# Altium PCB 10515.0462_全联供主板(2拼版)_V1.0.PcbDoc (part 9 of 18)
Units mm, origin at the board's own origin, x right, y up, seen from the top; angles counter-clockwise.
Board outline 282 x 198 mm, 2 copper layers (Top Layer, Bottom Layer); 716 components, 0 nets, 2364 pads, 1800 vias.
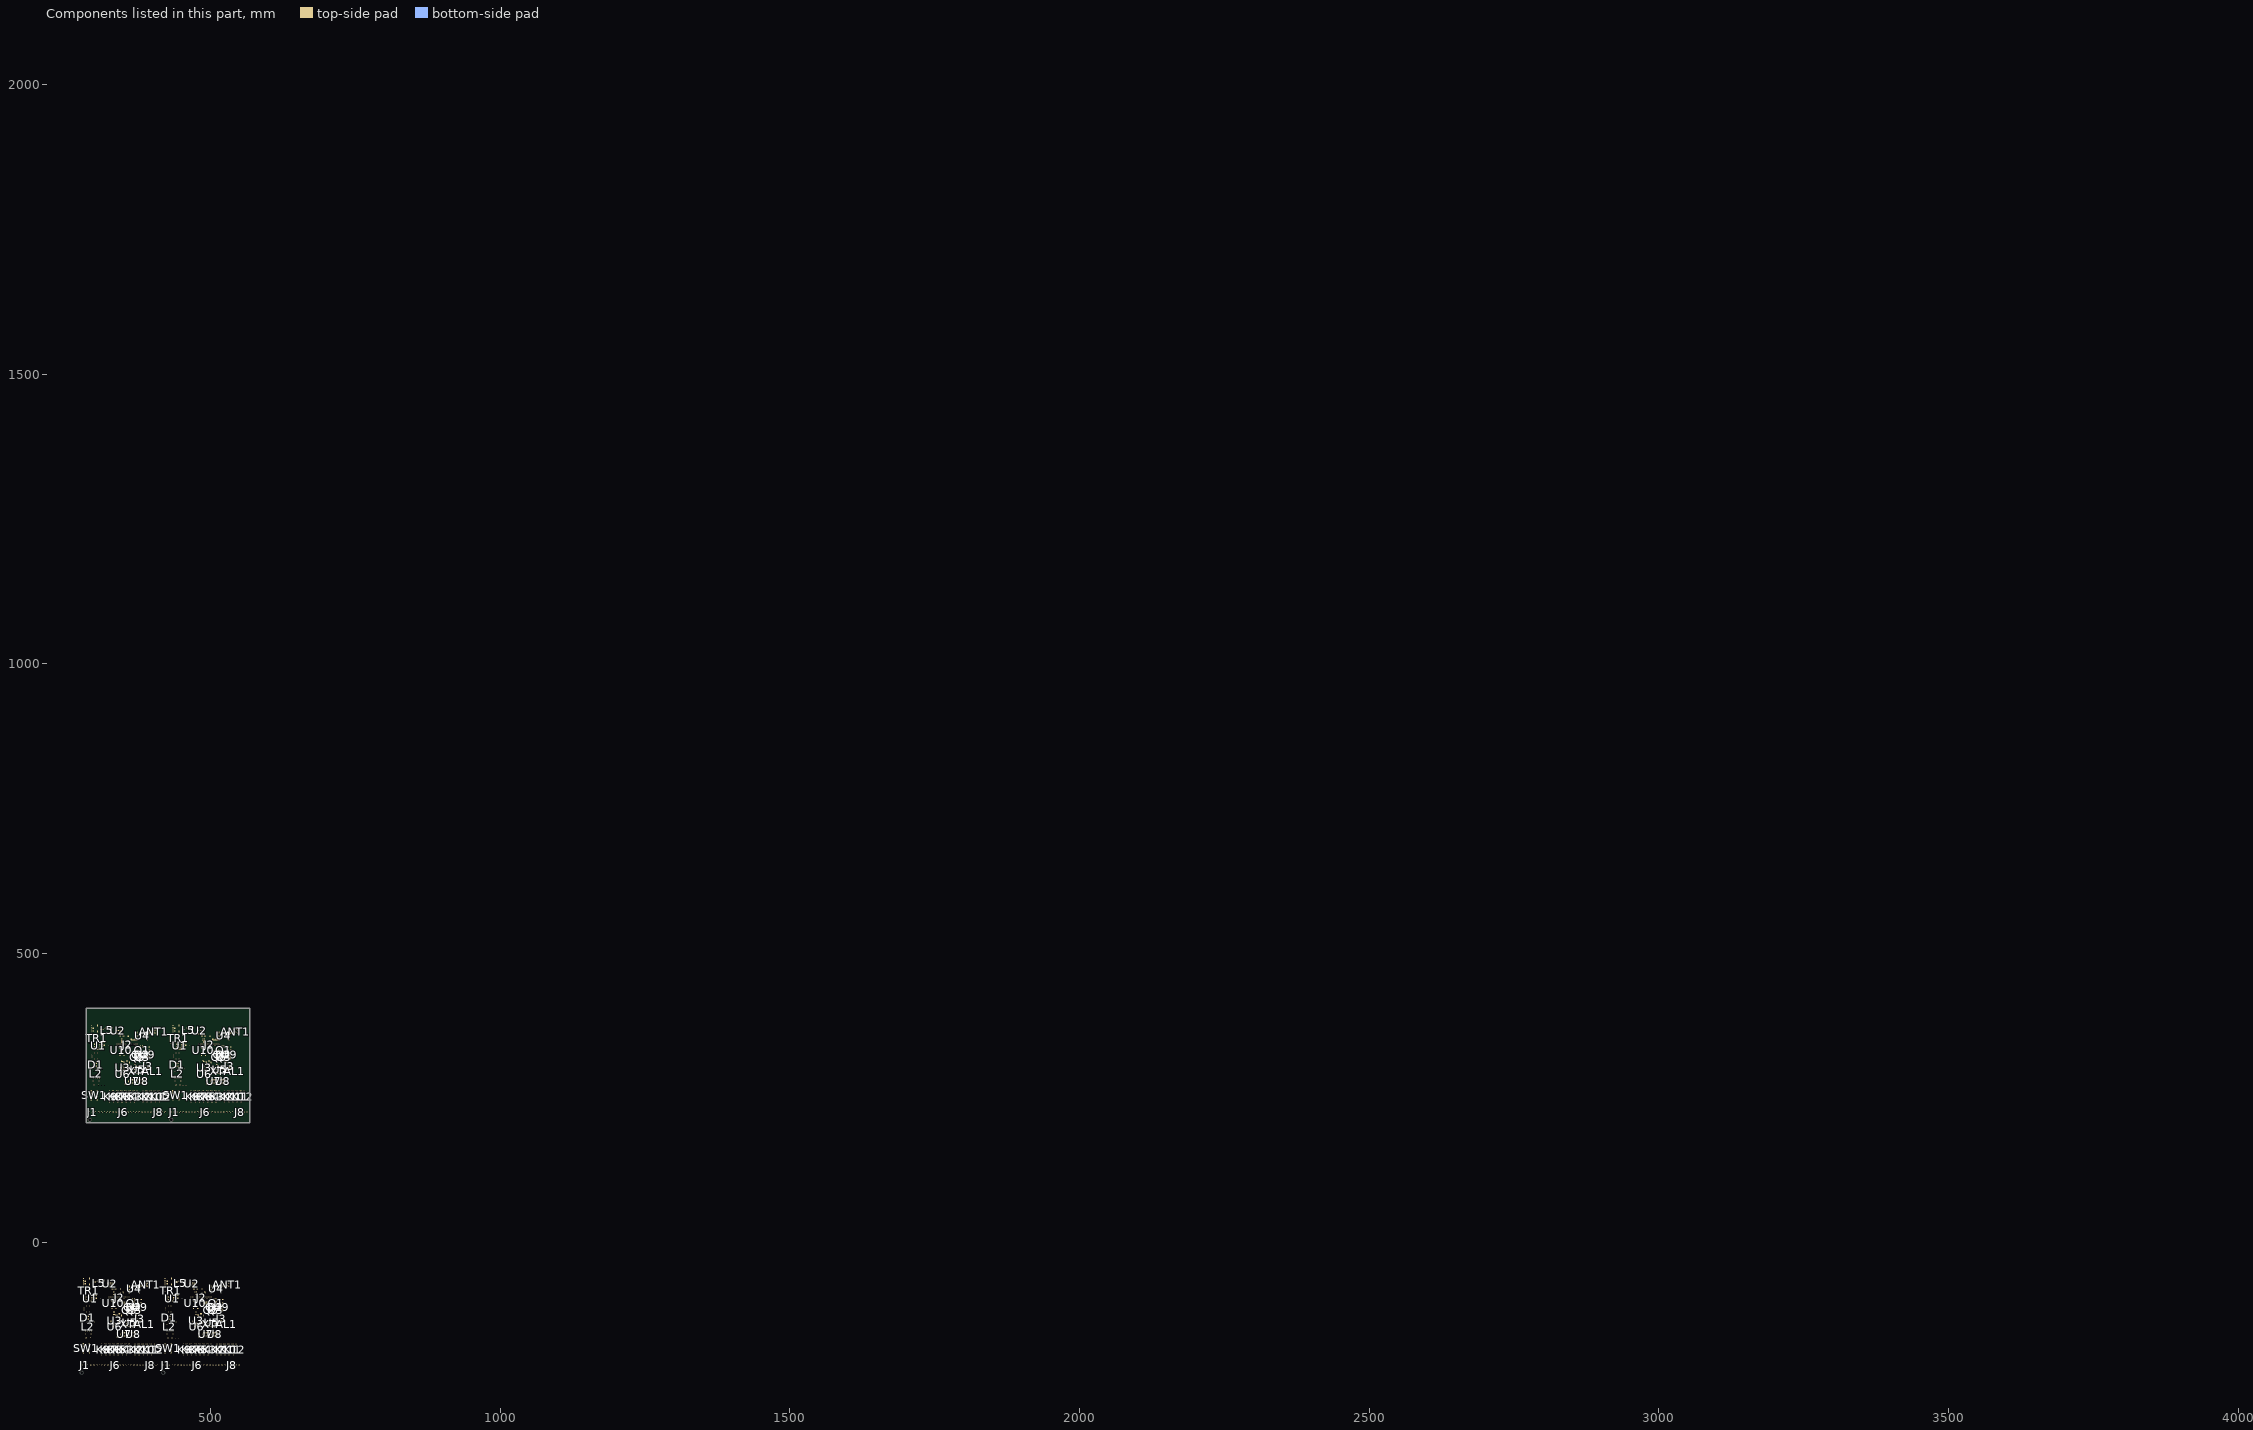
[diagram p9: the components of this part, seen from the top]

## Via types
v1: diameter 0.7, hole 0.4, Top Layer to Bottom Layer, tented both sides, 1800 vias

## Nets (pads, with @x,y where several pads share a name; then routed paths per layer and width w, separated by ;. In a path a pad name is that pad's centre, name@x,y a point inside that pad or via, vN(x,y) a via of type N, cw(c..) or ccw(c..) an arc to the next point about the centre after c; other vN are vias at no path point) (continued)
copper on no net: (continued)
  Top Layer w0.65: 285.476,-64.542 287.715,-64.542 290.89,-61.367 290.89,-62.336 295.122,-66.568 295.509,-66.568 ; 290.89,-71.667 290.89,-71.51 292.366,-70.035 ; 291.064,-69.749 292.614,-68.2 297.083,-68.2 296.55,-68.733 292.842,-68.733 292.461,-69.114 ; 291.318,-61.875 295.509,-66.066 296.601,-66.066 ; 291.318,-61.113 296.754,-66.549 296.837,-66.549 296.96,-66.426 ; 291.572,-70.003 292.144,-69.431 ; 292.017,-63.462 292.017,-64.288 ; 292.652,-64.923 292.017,-64.923 ; 293.35,-64.034 295.001,-65.685 296.22,-65.685 297.083,-66.549 ; 293.604,-66.568 293.604,-66.51 292.017,-64.923 ; 294.297,-66.568 292.017,-64.288 ; 295.691,-68.733 ccw(c295.691,-66.845) 297.026,-68.18 ; 295.813,-66.066 cw(c295.813,-67.78) 297.026,-66.568 295.509,-66.568 ; 297.083,-66.429 ccw(c297.083,-65.893) 297.462,-66.272 ; 297.141,-66.568 cw(c298.353,-67.78) 298.353,-66.066 ; 297.16,-68.479 296.208,-69.431 ; 297.164,-66.519 cw(c297.668,-66.573) 297.668,-66.066 ; 298.801,-66.565 ccw(c297.668,-67.601) 297.668,-66.066 ; 298.861,-66.549 298.379,-66.066 297.668,-66.066 ; 299.105,372.053 301.344,372.053 304.519,375.228 304.519,374.259 308.751,370.027 309.138,370.027 ; 299.738,-66.637 cw(c300.203,-67.102) 300.547,-66.542 ; 300.097,-65.669 cw(c301.224,-66.795) v1@301.224,-65.202 ; 300.272,-65.494 cw(c301.023,-66.246) v1@301.219,-65.202 ; 300.532,-66.415 ccw(c299.473,-65.356) v1@300.97,-65.356 ; v1@300.571,-65.195 cw(c299.609,-66.157) 300.97,-66.157 ; 300.589,-66.654 cw(c302.547,-66.654) v1@301.241,-65.196 ; 300.589,-66.391 ccw(c300.589,-65.336) 301.335,-66.082 ; v1@300.594,-65.202 cw(c300.79,-66.246) 301.542,-65.494 ; 300.612,-66.394 cw(c300.82,-65.685) 300.081,-65.685 ; 300.97,-65.851 cw(c301.898,-65.851) v1@301.242,-65.195 ; 300.995,-66.549 ccw(c300.995,-62.838) 303.619,-65.462 cw(c302.467,-64.309) 302.467,-65.939 cw(c302.467,-67.569) 303.619,-66.416 ; v1@301.206,-65.195 cw(c300.551,-65.851) 301.478,-65.851 ; 302.564,-66.549 ccw(c302.564,-64.407) 304.078,-65.921 ; 304.519,364.928 304.519,365.085 305.995,366.561 ; 304.693,366.846 306.242,368.396 310.712,368.396 310.178,367.862 306.471,367.862 306.09,367.481 ; 304.947,374.72 309.138,370.529 310.229,370.529 ; 304.947,375.482 310.382,370.047 310.466,370.047 310.589,370.17 ; 305.201,366.592 305.772,367.164 ; 305.645,373.133 305.645,372.307 ; 306.28,371.672 305.645,371.672 ; 306.979,372.561 308.63,370.91 309.848,370.91 310.712,370.047 ; 307.233,370.027 307.233,370.085 305.645,371.672 ; 307.925,370.027 305.645,372.307 ; 308.494,-66.416 cw(c307.342,-67.569) 308.971,-67.569 cw(c310.601,-67.569) 309.448,-66.416 ; 308.504,-73.001 ccw(c307.457,-71.908) 308.971,-71.908 ccw(c310.485,-71.908) 309.438,-73.001 ; 308.735,-66.571 cw(c308.266,-67.827) 309.606,-67.827 ; 308.962,-65.962 cw(c308.616,-66.89) 309.606,-66.89 ; 308.971,-66.614 cw(c308.971,-69.163) 310.774,-67.361 ; 308.996,-73.486 cw(c310.514,-73.292) 309.432,-72.209 ; 308.998,-72.815 ccw(c309.059,-71.234) 310.178,-72.353 ; 309.281,-72.889 cw(c309.941,-71.613) 308.504,-71.613 ; 309.32,367.862 ccw(c309.32,369.75) 310.654,368.415 ; 309.442,370.529 cw(c309.442,368.815) 310.654,370.027 309.138,370.027 ; 309.606,-67.082 310.368,-67.844 312.4,-67.844 ; 309.635,-66.059 ccw(c311.337,-66.367) 310.114,-67.59 ; 309.641,-73.403 cw(c312.174,-73.079) 310.368,-71.273 ; 309.646,-73.489 cw(c311.107,-73.489) 310.074,-72.456 ; 309.646,-65.939 ccw(c310.356,-65.939) 309.854,-66.441 ; 310.712,370.166 ccw(c310.712,370.702) 311.091,370.323 ; 310.769,370.027 cw(c311.982,368.815) 311.982,370.529 ; 310.789,368.116 309.836,367.164 ; 310.793,370.076 cw(c311.297,370.023) 311.297,370.529 ; 312.43,370.03 ccw(c311.297,368.995) 311.297,370.529 ; 312.49,370.047 312.007,370.529 311.297,370.529 ; 313.035,-68.479 314.813,-66.701 314.813,-66.574 ; 313.035,-67.844 313.035,-67.543 315.655,-64.923 ; 313.162,-67.844 314.813,-66.193 ; 313.257,-67.241 cw(c315.655,-69.64) 315.655,-66.248 ; 313.282,-66.581 cw(c315.655,-68.954) 315.655,-65.598 ; 313.289,-71.781 314.305,-72.797 314.305,-74.448 315.08,-75.223 315.655,-75.223 ; 313.367,369.958 cw(c313.832,369.493) 314.175,370.054 ; 313.393,-67.185 cw(c315.655,-69.447) 315.655,-66.248 ; 313.67,-67.844 312.4,-67.844 ; 313.71,370.91 ccw(c314.449,370.91) 314.241,370.201 ; 313.726,370.927 cw(c314.853,369.8) v1@314.853,371.393 ; 313.9,371.101 cw(c314.652,370.35) v1@314.848,371.394 ; 314.124,-66.882 cw(c315.655,-68.414) 315.655,-66.248 ; 314.16,370.181 ccw(c313.102,371.239) v1@314.599,371.239 ; v1@314.2,371.401 cw(c313.238,370.438) 314.599,370.438 ; 314.218,369.942 cw(c316.175,369.942) v1@314.87,371.4 ; 314.218,370.204 ccw(c314.218,371.259) 314.964,370.513 ; v1@314.223,371.394 cw(c314.419,370.35) 315.17,371.101 ; 314.366,-66.132 cw(c315.655,-67.421) 315.655,-65.598 ; 314.392,-65.471 cw(c315.655,-66.735) 315.655,-64.948 ; 314.432,-72.543 313.67,-71.781 310.749,-71.781 310.178,-72.352 ; 314.503,-66.075 cw(c315.655,-67.228) 315.655,-65.598 ; 314.599,370.745 cw(c315.526,370.745) v1@314.871,371.401 ; 314.624,370.047 ccw(c314.624,373.758) 317.248,371.134 cw(c316.095,372.286) 316.095,370.656 cw(c316.095,369.027) 317.248,370.179 ; 314.663,-66.851 ccw(c313.534,-65.723) 315.13,-65.723 ; 314.813,-74.261 ccw(c315.817,-74.261) 315.107,-74.971 ; 314.813,-72.692 ccw(c317.386,-72.692) 315.567,-74.511 ; 314.813,-72.289 313.797,-71.273 310.368,-71.273 308.971,-72.67 308.971,-73.489 ; 314.813,-71.527 314.051,-70.765 310.114,-70.765 308.971,-71.908 308.971,-73.489 ; 314.813,-71.123 ccw(c318.955,-71.123) 316.026,-74.052 cw(c316.923,-73.156) 315.655,-73.156 cw(c314.388,-73.156) 315.284,-74.052 ; 314.813,-68.123 cw(c317.079,-68.123) 315.923,-66.175 ; 314.813,-67.971 313.924,-68.86 ; 314.813,-67.336 313.67,-68.479 310.368,-68.479 309.606,-67.717 309.606,-66.574 308.971,-65.939 ; 314.813,-66.982 cw(c316.402,-66.982) 315.591,-65.615 ; v1@314.835,371.401 cw(c314.179,370.745) 315.107,370.745 ; 314.881,-66.633 ccw(c314.226,-65.978) 315.138,-65.815 ; 314.94,-64.923 312.527,-67.336 310.749,-67.336 309.352,-65.939 308.971,-65.939 ; 315.284,-75.594 ccw(c314.388,-76.49) 314.388,-75.223 ccw(c314.388,-73.956) 315.284,-74.852 ; 315.321,-75.223 314.318,-75.223 313.924,-74.829 313.924,-73.305 312.972,-72.352 310.178,-72.352 ; 315.325,-74.015 ccw(c313.829,-72.162) 316.21,-72.162 ; 315.465,-73.934 ccw(c314.827,-72.289) 316.591,-72.289 ; 315.578,-74.522 ccw(c316.044,-73.925) 316.579,-74.46 ; 315.655,-65.859 315.655,-64.923 ; 315.7,-74.54 ccw(c315.196,-73.238) 316.591,-73.238 ; 315.734,-74.52 ccw(c314.928,-73.523) 316.21,-73.523 ; 315.935,-75.146 ccw(c315.564,-74.188) 316.591,-74.188 ; 315.978,-74.009 ccw(c316.5,-73.34) 317.099,-73.94 ; 316.026,-66.094 ccw(c316.923,-66.99) 315.655,-66.99 ccw(c314.388,-66.99) 315.284,-66.094 cw(c313.354,-68.024) 316.083,-68.024 ; 316.106,-75.491 cw(c316.578,-75.772) 316.578,-75.223 ; 316.106,-74.955 ccw(c316.578,-74.674) 316.578,-75.223 ; 316.18,-65.723 ccw(c318.162,-65.723) 316.761,-67.125 ; 316.193,370.047 ccw(c316.193,372.189) 317.707,370.674 ; 317.353,-71.527 316.591,-72.289 316.591,-74.575 315.943,-75.223 315.655,-75.223 ; 317.516,-68.733 cw(c317.516,-70.094) v1@318.478,-69.132 ; 317.933,-69.278 ccw(c317.933,-67.609) v1@319.113,-68.789 ; 317.988,-71.527 317.099,-72.416 317.099,-73.94 ; 318.04,-69.278 ccw(c318.04,-68.658) v1@318.478,-69.096 ; 318.274,-68.638 cw(c317.798,-69.114) v1@318.471,-69.114 ; v1@318.514,-69.132 cw(c319.476,-70.094) 319.476,-68.733 ; v1@318.514,-69.096 ccw(c318.952,-68.658) 318.952,-69.278 ; v1@318.517,-69.128 cw(c319.131,-69.554) v1(319.131,-68.807) 318.443,-68.807 316.083,-66.447 ; 318.517,-68.733 cw(c318.517,-70.653) v1@319.875,-69.295 ; v1@319.154,-68.797 ccw(c319.893,-68.47) v1(319.893,-69.278) ; 319.675,-68.733 cw(c319.675,-70.094) v1@320.637,-69.132 ; v1@319.915,-69.29 cw(c320.872,-69.834) 320.872,-68.733 ; v1@320.199,-69.278 ccw(c320.199,-68.658) v1@320.637,-69.096 ; 320.285,-71.527 ccw(c320.285,-69.418) 321.776,-70.909 ; v1@320.673,-69.096 ccw(c321.111,-68.658) 321.111,-69.278 ; 320.909,-72.416 320.655,-72.162 ; 320.909,-71.867 321.834,-70.942 ; 321.1,-68.961 ccw(c321.635,-68.425) 321.815,-69.161 ; 321.157,-70.809 ccw(c321.48,-70.486) 321.78,-70.829 ; 321.29,-70.942 320.859,-70.511 316.464,-70.511 315.655,-71.32 315.655,-72.543 ; 321.417,-69.278 320.872,-68.733 ; 321.753,-72.67 321.753,-72.031 321.249,-71.527 ; 321.834,-70.929 321.834,-70.942 ; 321.834,-69.278 v1(319.893,-69.278) ; 321.847,-70.942 321.834,-70.942 ; 322.123,370.179 cw(c320.97,369.027) 322.6,369.027 cw(c324.229,369.027) 323.077,370.179 ; 322.133,363.594 ccw(c321.086,364.687) 322.6,364.687 ccw(c324.114,364.687) 323.067,363.594 ; 322.364,370.024 cw(c321.894,368.769) 323.235,368.769 ; 322.484,-73.99 322.243,-73.749 ; 322.525,-73.441 321.036,-71.953 321.036,-71.527 ; 322.591,370.633 cw(c322.244,369.705) 323.235,369.705 ; 322.6,369.981 cw(c322.6,367.432) 324.403,369.235 ; 322.625,363.11 cw(c324.143,363.304) 323.061,364.386 ; 322.626,363.781 ccw(c322.688,365.361) 323.806,364.243 ; 322.91,363.706 cw(c323.57,364.983) 322.133,364.983 ; 323.235,369.513 323.997,368.751 326.029,368.751 ; 323.264,370.536 ccw(c324.965,370.228) 323.743,369.006 ; 323.269,363.192 cw(c325.803,363.516) 323.997,365.322 ; 323.275,363.106 cw(c324.735,363.106) 323.703,364.139 ; 323.275,370.656 ccw(c323.985,370.656) 323.483,370.155 ; 324.272,-96.104 cw(c323.526,-96.85) 324.581,-96.85 cw(c325.636,-96.85) 324.89,-96.104 cw(c325.636,-96.85) 325.636,-95.795 cw(c325.636,-94.74) 324.89,-95.486 cw(c325.636,-94.74) 324.581,-94.74 cw(c323.526,-94.74) 324.272,-95.486 ; 324.272,-93.564 cw(c323.526,-94.31) 324.581,-94.31 cw(c325.636,-94.31) 324.89,-93.564 cw(c325.664,-94.338) 325.664,-93.244 ; 324.369,-95.413 ccw(c323.799,-94.387) 324.973,-94.387 ; 324.4,-95.683 cw(c325.821,-96.57) 325.821,-94.895 ; 324.427,-93.664 cw(c324.131,-94.453) 324.973,-94.453 ; 324.43,-93.405 ccw(c325.564,-92.283) 325.564,-93.879 ; 324.468,-95.976 ccw(c324.926,-95.242) 325.538,-95.854 ; 324.592,-93.244 327.11,-93.244 327.121,-93.255 ; 324.812,-95.425 ccw(c325.371,-94.531) 326.116,-95.276 ; 324.89,-92.946 ccw(c325.608,-92.228) 325.608,-93.244 ; 324.892,-92.948 ccw(c327.121,-90.744) 327.121,-93.879 ; 324.952,-96.027 cw(c326.994,-97.303) 326.994,-94.895 324.973,-94.895 ; 324.973,-96.419 326.116,-95.276 ; 324.973,-96.188 324.973,-94.895 ; 324.973,-95.988 cw(c326.116,-96.549) 326.116,-95.276 ; 326.017,-94.895 cw(c326.017,-96.338) 327.312,-95.701 ; 326.038,-93.244 cw(c326.038,-94.338) 326.812,-93.564 cw(c326.066,-94.31) 327.121,-94.31 cw(c328.176,-94.31) 327.43,-93.564 ; 326.094,-93.244 ccw(c326.094,-92.228) 326.812,-92.946 ; 326.379,-93.879 ccw(c326.379,-92.79) 327.301,-93.369 ; 326.664,368.116 328.442,369.894 328.442,370.021 ; 326.664,368.751 326.664,369.052 329.284,371.672 ; 326.685,-95.817 ccw(c326.116,-95.845) 326.116,-95.276 ; 326.729,-95.988 ccw(c324.973,-96.851) 324.973,-94.895 ; 326.751,-93.023 cw(c325.205,-92.054) 325.205,-93.879 327.121,-93.879 327.121,-93.255 ; 326.791,368.751 328.442,370.402 ; 326.812,-96.104 ccw(c326.066,-96.85) 326.066,-95.795 ccw(c326.066,-94.74) 326.812,-95.486 ccw(c326.066,-94.74) 327.121,-94.74 ccw(c328.176,-94.74) 327.43,-95.486 ; 326.885,369.354 cw(c329.284,366.956) 329.284,370.347 ; 326.911,370.015 cw(c329.284,367.642) 329.284,370.997 ; 326.918,364.814 327.934,363.798 327.934,362.147 328.709,361.372 329.284,361.372 ; 327.022,369.411 cw(c329.284,367.149) 329.284,370.347 ; 327.121,-95.276 326.116,-95.276 ; 327.121,-94.387 324.973,-94.387 ; 327.299,368.751 326.029,368.751 ; 327.753,369.713 cw(c329.284,368.182) 329.284,370.347 ; 327.995,370.464 cw(c329.284,369.175) 329.284,370.997 ; 328.021,371.124 cw(c329.284,369.861) 329.284,371.647 ; 328.061,364.052 327.299,364.814 324.378,364.814 323.806,364.243 ; 328.132,370.52 cw(c329.284,369.368) 329.284,370.997 ; 328.291,369.744 ccw(c327.163,370.872) 328.759,370.872 ; 328.442,362.334 ccw(c329.446,362.334) 328.736,361.624 ; 328.442,363.903 ccw(c331.015,363.903) 329.195,362.084 ; 328.442,364.306 327.426,365.322 323.997,365.322 322.6,363.925 322.6,363.106 ; 328.442,365.068 327.68,365.83 323.743,365.83 322.6,364.687 322.6,363.106 ; 328.442,365.473 ccw(c332.584,365.473) 329.655,362.544 cw(c330.551,363.44) 329.284,363.44 cw(c328.016,363.44) 328.913,362.544 ; 328.442,368.472 cw(c330.708,368.472) 329.552,370.421 ; 328.442,368.624 327.553,367.735 ; 328.442,369.259 327.299,368.116 323.997,368.116 323.235,368.878 323.235,370.021 322.6,370.656 ; 328.442,369.613 cw(c330.031,369.613) 329.22,370.98 ; 328.51,369.963 ccw(c327.855,370.618) 328.767,370.78 ; 328.569,371.672 326.156,369.259 324.378,369.259 322.981,370.656 322.6,370.656 ; 328.913,361.001 ccw(c328.016,360.105) 328.016,361.372 ccw(c328.016,362.64) 328.913,361.744 ; 328.95,361.372 327.947,361.372 327.553,361.766 327.553,363.29 326.6,364.243 323.806,364.243 ; 328.954,362.581 ccw(c327.457,364.433) 329.839,364.433 ; 329.094,362.662 ccw(c328.456,364.306) 330.22,364.306 ; 329.207,362.074 ccw(c329.673,362.671) 330.208,362.136 ; 329.284,370.736 329.284,371.672 ; 329.329,362.056 ccw(c328.824,363.357) 330.22,363.357 ; 329.352,-95.486 ccw(c328.606,-94.74) 329.661,-94.74 ccw(c330.716,-94.74) 329.97,-95.486 ; 329.352,-93.564 cw(c328.606,-94.31) 329.661,-94.31 cw(c330.716,-94.31) 329.97,-93.564 ; 329.352,-92.946 ccw(c328.606,-92.2) 329.661,-92.2 ccw(c330.716,-92.2) 329.97,-92.946 ; 329.362,362.075 ccw(c328.557,363.073) 329.839,363.073 ; 329.474,-113.477 cw(c329.474,-114.971) 330.531,-113.915 ; 329.499,-112.8 ccw(c330.612,-112.7) 330.612,-113.818 ; 329.529,-113.475 cw(c329.601,-114.341) 330.216,-113.726 cw(c330.633,-113.309) 330.092,-113.073 ; 329.535,-113.474 cw(c329.633,-114.563) 330.406,-113.79 cw(c331.093,-113.103) 330.138,-112.925 ; 329.564,361.45 ccw(c329.193,362.408) 330.22,362.408 ; 329.607,362.586 ccw(c330.128,363.255) 330.728,362.655 ; 329.655,370.501 ccw(c330.551,369.605) 329.284,369.605 ccw(c328.016,369.605) 328.913,370.501 cw(c326.983,368.572) 329.712,368.572 ; 329.661,-100.366 329.661,-95.795 ; 329.661,-99.135 ccw(c330.596,-99.135) 329.935,-99.796 ; 329.735,361.104 cw(c330.207,360.824) 330.207,361.372 ; 329.735,361.641 ccw(c330.207,361.921) 330.207,361.372 ; 329.776,-100.481 329.776,-95.91 329.661,-95.795 ; 329.776,-97.128 ccw(c328.329,-97.128) 329.352,-96.104 cw(c328.606,-96.85) 329.661,-96.85 cw(c330.716,-96.85) 329.97,-96.104 ccw(c330.439,-96.573) 329.776,-96.573 ; 329.809,370.872 ccw(c331.791,370.872) 330.389,369.471 ; 329.951,-113.279 cw(c331.104,-114.432) 331.104,-112.802 cw(c331.104,-111.172) 329.951,-112.325 ; 330.12,-112.998 cw(c331.069,-113.286) 331.069,-112.294 ; 330.146,-112.742 ccw(c331.323,-112.637) 331.323,-113.818 ; 330.149,-112.802 ccw(c331.914,-112.802) 330.666,-114.05 ; 330.434,-113.818 331.831,-115.215 331.831,-118.39 332.238,-118.796 332.238,-119.329 ; 330.982,365.068 330.22,364.306 330.22,362.02 329.572,361.372 329.284,361.372 ; 331.021,-106.75 ccw(c329.37,-105.1) 331.704,-105.1 ; 331.145,367.862 cw(c331.145,366.501) v1@332.107,367.464 ; 331.531,-121.612 cw(c329.824,-123.318) 332.238,-123.318 ; 331.531,-121.01 ccw(c329.824,-119.304) 332.238,-119.304 ; 331.562,367.318 ccw(c331.562,368.987) v1@332.742,367.807 ; 331.617,365.068 330.728,364.179 330.728,362.655 ; 331.669,367.318 ccw(c331.669,367.937) v1@332.107,367.499 ; 331.695,-107.811 cw(c330.415,-109.091) 332.226,-109.091 cw(c334.036,-109.091) 332.756,-107.811 ; 331.695,-106.75 ccw(c330.777,-105.832) 332.076,-105.832 ; 331.704,-107.802 331.704,-108.865 ; 331.704,-105.84 ccw(c332.991,-105.84) 332.081,-106.75 ; 331.704,-102.446 cw(c333.516,-102.446) 332.235,-101.165 ; 331.704,-98.515 ccw(c333.516,-98.515) 332.235,-99.796 ; 331.704,-98.05 cw(c334.456,-98.05) 332.51,-96.104 ccw(c333.558,-97.153) 332.076,-97.153 ; 331.704,-96.481 cw(c332.886,-96.481) 332.05,-95.645 ; 331.704,-95.51 cw(c334.456,-95.51) 332.51,-93.564 ccw(c333.256,-94.31) 332.201,-94.31 ccw(c331.146,-94.31) 331.892,-93.564 ; 331.704,-95.174 ccw(c332.738,-95.174) 332.062,-95.956 ; 331.704,-93.941 cw(c332.886,-93.941) 332.05,-93.105 ; 331.812,-91.231 ccw(c331.063,-90.481) 332.118,-90.381 ; 331.881,-87.133 cw(c331.019,-87.995) 332.238,-87.995 ; 331.892,-96.104 cw(c331.448,-96.548) 332.076,-96.548 ; 331.892,-95.486 ccw(c331.146,-94.74) 332.201,-94.74 ccw(c333.256,-94.74) 332.51,-95.486 ; 331.903,367.958 cw(c331.426,367.481) v1@332.1,367.481 ; 332.076,-107.131 332.076,-100.481 332.076,-95.921 ; 332.076,-105.108 ccw(c334.399,-105.108) 332.756,-106.75 ; 332.076,-104.792 332.847,-105.563 332.847,-111.278 332.226,-111.899 ; v1@332.143,367.464 cw(c333.105,366.501) 333.105,367.862 ; v1@332.143,367.499 ccw(c332.581,367.937) 332.581,367.318 ; v1@332.145,367.467 cw(c332.76,367.041) v1(332.76,367.789) 332.072,367.789 329.712,370.148 ; 332.146,367.862 cw(c332.146,365.942) v1@333.504,367.3 ; 332.201,-95.795 332.201,-93.255 331.704,-93.752 ; 332.218,-123.451 cw(c331.313,-124.356) 332.593,-124.356 ; 332.226,-107.281 332.226,-111.899 ; 332.228,-123.459 cw(c331.713,-124.173) 332.593,-124.173 ; 332.238,-86.939 332.238,-88.849 332.238,-90.806 331.577,-91.466 330.18,-91.466 329.661,-91.985 329.661,-93.255 329.661,-95.795 ; 332.344,-123.437 ccw(c332.663,-123.64) 332.396,-123.908 ; 332.37,-107.811 cw(c331.22,-108.962) 332.847,-108.962 ; 332.37,-106.75 ccw(c331.22,-105.6) 332.847,-105.6 ; 332.429,-130.582 cw(c332.429,-131.948) 333.395,-130.982 ; 332.487,-95.465 cw(c333.969,-93.752) 331.704,-93.752 ; 332.593,-125.629 332.593,-125.248 ; v1@332.783,367.799 ccw(c333.522,368.126) v1(333.522,367.318) ; 332.847,-109.221 cw(c334.841,-109.221) 333.431,-107.811 ; 332.847,-105.563 ccw(c334.334,-105.563) 333.381,-106.705 ; 333.304,367.862 cw(c333.304,366.501) v1@334.266,367.464 ; 333.355,-125.985 332.619,-125.248 332.593,-125.248 ; 333.371,-130.926 ccw(c333.021,-130.932) 333.021,-130.582 ; 333.491,-131.051 333.021,-130.582 ; v1@333.544,367.305 cw(c334.501,366.761) 334.501,367.862 ; v1@333.828,367.318 ccw(c333.828,367.937) v1@334.266,367.499 ; 333.869,-119.387 cw(c332.657,-120.599) 334.371,-120.599 ; 333.869,-88.791 ccw(c332.681,-87.604) 334.361,-87.604 ; 333.889,-91.11 334.741,-91.963 334.741,-93.255 ; 333.889,-88.744 cw(c336.166,-88.744) 334.556,-87.133 ccw(c335.025,-87.603) 334.361,-87.603 ; 333.909,-119.408 cw(c333.78,-119.985) 334.371,-119.985 ; 333.914,365.068 ccw(c333.914,367.177) 335.405,365.686 ; 334.008,-123.389 cw(c335.251,-123.334) 334.371,-122.454 ; 334.008,-119.329 cw(c335.092,-119.329) 334.325,-118.563 ; 334.167,-87.133 cw(c333.697,-87.603) 334.361,-87.603 ; 334.217,-101.165 cw(c332.311,-103.07) 335.006,-103.07 ; 334.217,-99.796 ccw(c332.311,-97.891) 335.006,-97.891 ; 334.244,-99.97 334.244,-95.022 ; 334.244,-99.094 ccw(c335.237,-99.094) 334.535,-99.796 ; 334.244,-98.05 cw(c336.996,-98.05) 335.05,-96.104 ; 334.244,-96.481 cw(c335.426,-96.481) 334.59,-95.645 ; 334.244,-95.11 ccw(c335.426,-95.11) 334.59,-95.946 ; 334.244,-95.09 cw(c336.077,-95.09) 334.998,-93.609 ; 334.244,-93.541 ccw(c336.996,-93.541) 335.05,-95.486 ; v1@334.302,367.499 ccw(c334.74,367.937) 334.74,367.318 ; 334.376,-101.231 cw(c334.376,-103.024) 335.644,-101.756 ; 334.376,-97.732 cw(c336.678,-97.732) 335.05,-96.104 ; 334.376,-96.161 334.376,-100.481 334.376,-103.663 335.006,-104.293 ; 334.422,-123.926 ccw(c335.068,-123.279) 335.633,-123.999 ; 334.432,-96.104 cw(c333.046,-97.49) 335.006,-97.49 ; 334.432,-95.486 ccw(c333.686,-94.74) 334.741,-94.74 ccw(c335.796,-94.74) 335.05,-95.486 ; 334.432,-93.564 cw(c333.686,-94.31) 334.741,-94.31 cw(c335.796,-94.31) 335.05,-93.564 cw(c335.796,-94.31) 335.796,-93.255 cw(c335.796,-92.2) 335.05,-92.946 ; 334.432,-92.946 ccw(c333.686,-92.2) 334.741,-92.2 ccw(c335.796,-92.2) 335.05,-92.946 ; 334.46,-101.214 cw(c334.74,-101.902) 335.265,-101.377 ; 334.538,364.179 334.284,364.433 ; 334.538,364.728 335.463,365.653 ; 334.562,-93.371 ccw(c335.961,-92.468) 335.961,-94.133 ; 334.57,-95.668 cw(c335.858,-96.629) 335.858,-95.022 ; 334.576,-113.613 cw(c336.474,-115.512) 336.474,-112.827 ; 334.586,-95.942 ccw(c335.4,-95.171) 335.4,-96.292 ; 334.676,-100.705 cw(c333.88,-101.501) 335.006,-101.501 ; 334.676,-100.256 ccw(c333.88,-99.46) 335.006,-99.46 ; 334.729,367.635 ccw(c335.264,368.17) 335.443,367.435 ; 334.767,-114.184 cw(c336.474,-115.891) 336.474,-113.477 ; 334.785,365.787 ccw(c335.108,366.11) 335.409,365.766 ; 334.829,-124.334 333.889,-123.393 ; 334.832,-92.828 cw(c334.988,-92.101) 334.244,-92.101 ; 334.844,-113.345 cw(c335.455,-113.957) 336.028,-113.308 ; 334.879,-92.736 336.403,-92.736 ; 334.919,365.653 334.488,366.084 330.093,366.084 329.284,365.275 329.284,364.052 ; 334.94,-124.445 ccw(c335.524,-123.861) 336.034,-124.511 ; 335.006,-104.471 cw(c335.868,-104.471) v1@335.524,-103.681 ; 335.006,-102.371 ccw(c336.801,-102.371) v1@335.532,-103.64 ; 335.006,-101.118 335.514,-101.626 335.514,-111.024 336.474,-111.984 336.474,-112.802 ; 335.006,-96.927 335.641,-96.292 336.911,-96.292 ; 335.006,-96.061 335.006,-104.293 ; 335.046,367.318 334.501,367.862 ; 335.058,-95.495 ccw(c336.911,-93.74) 336.911,-96.292 ; 335.091,-96.057 cw(c337.154,-97.595) 337.154,-95.022 334.244,-95.022 ; 335.108,-93.018 ccw(c337.154,-91.698) 337.154,-94.133 334.741,-94.133 ; 335.119,-93.475 cw(c336.403,-94.221) 336.403,-92.736 ; 335.142,-131.051 335.142,-130.082 334.371,-129.312 325.989,-129.312 325.227,-129.312 324.581,-128.666 324.581,-95.795 ; 335.333,-112.856 cw(c335.914,-113.437) 336.458,-112.821 ; 335.382,363.925 335.382,364.565 334.878,365.068 ; 335.463,365.667 335.463,365.653 ; 335.463,367.318 v1(333.522,367.318) ; 335.476,365.653 335.463,365.653 ; 335.552,-113.399 ccw(c334.954,-112.802) 335.799,-112.802 ccw(c334.17,-112.802) 335.322,-111.65 ccw(c336.474,-110.497) 336.474,-112.127 ; 335.595,-124.634 ccw(c334.869,-125.36) 334.869,-124.334 ccw(c334.869,-123.308) 335.595,-124.033 ; 335.869,-113.101 ccw(c335.387,-113.34) 335.387,-112.802 ; 335.869,-112.503 cw(c335.387,-112.264) 335.387,-112.802 ; 336.027,-111.537 cw(c334.973,-112.591) 336.449,-112.799 ; 336.112,362.605 335.871,362.846 ; 336.149,-112.802 334.371,-114.58 334.371,-118.517 333.889,-119 333.889,-119.329 334.371,-119.812 334.371,-122.454 333.889,-122.937 333.889,-123.393 ; 336.153,363.154 334.665,364.642 334.665,365.068 ; 336.196,-124.634 cw(c336.921,-125.36) 336.921,-124.334 cw(c336.921,-123.308) 336.196,-124.033 ; 336.292,-96.292 ccw(c336.292,-95.069) 337.157,-95.934 ; 336.403,-93.128 336.403,-92.736 ; 336.544,-95.403 cw(c336.544,-96.27) 337.157,-95.657 ; 336.599,-93.625 ccw(c336.599,-92.835) 337.157,-93.394 ; 336.688,-93.625 cw(c336.688,-91.308) 335.05,-92.946 ; 336.743,-95.403 ccw(c336.743,-97.797) 335.05,-96.104 ; 336.784,-93.128 336.784,-88.164 ; 336.784,-91.371 ccw(c338.903,-91.371) 337.405,-92.87 ; 337.281,-95.403 335.133,-95.403 334.741,-95.795 ; 337.281,-94.641 334.741,-94.641 ; 337.281,-93.625 335.111,-93.625 334.741,-93.255 ; 337.281,-89.445 342.654,-84.072 342.654,-83.183 ; 337.281,-88.556 337.281,-93.255 ; 337.399,-87.402 342.236,-82.565 ; 337.901,340.491 cw(c337.155,339.745) 338.21,339.745 cw(c339.265,339.745) 338.519,340.491 cw(c339.265,339.745) 339.265,340.8 cw(c339.265,341.855) 338.519,341.109 cw(c339.265,341.855) 338.21,341.855 cw(c337.155,341.855) 337.901,341.109 ; 337.901,343.031 cw(c337.155,342.285) 338.21,342.285 cw(c339.265,342.285) 338.519,343.031 cw(c339.292,342.257) 339.292,343.351 ; 337.977,-126.104 cw(c337.977,-127.437) 338.92,-126.494 ; 337.978,-124.214 ccw(c337.992,-123.408) 338.562,-123.978 ; 337.998,341.182 ccw(c337.428,342.208) 338.602,342.208 ; 338.009,-126.098 cw(c338.237,-126.628) 338.645,-126.22 ; 338.029,340.913 cw(c339.45,340.025) 339.45,341.7 ; 338.035,-124.353 cw(c338.94,-125.259) 338.94,-123.978 ; 338.053,-124.325 cw(c338.562,-124.525) 338.562,-123.978 ; 338.056,342.931 cw(c337.759,342.143) 338.602,342.143 ; 338.058,343.19 ccw(c339.193,344.312) 339.193,342.716 ; 338.097,340.619 ccw(c338.555,341.353) 339.167,340.741 ; 338.221,343.351 340.738,343.351 340.75,343.34 ; 338.441,341.171 ccw(c339,342.065) 339.745,341.319 ; 338.519,343.649 ccw(c339.237,344.368) 339.237,343.351 ; 338.521,343.647 ccw(c340.75,345.851) 340.75,342.716 ; 338.58,340.568 cw(c340.623,339.292) 340.623,341.7 338.602,341.7 ; 338.602,340.176 339.745,341.319 ; 338.602,340.408 338.602,341.7 ; 338.602,340.607 cw(c339.745,340.046) 339.745,341.319 ; 339.636,-127.211 ccw(c340.396,-126.45) 341.028,-127.321 ; 339.646,341.7 cw(c339.646,340.257) 340.941,340.894 ; 339.667,343.351 cw(c339.667,342.257) 340.441,343.031 cw(c339.695,342.285) 340.75,342.285 cw(c341.805,342.285) 341.059,343.031 ; 339.722,343.351 ccw(c339.722,344.368) 340.441,343.649 ; 340.008,342.716 ccw(c340.008,343.805) 340.93,343.227 ; 340.144,-127.211 ccw(c340.655,-126.699) 341.053,-127.304 ; 340.175,-127.749 ccw(c340.849,-127.075) 341.409,-127.847 ; 340.257,-123.426 cw(c341.424,-124.592) 341.424,-122.943 ; 340.278,-123.406 ccw(c339.14,-122.268) 340.749,-122.268 ; 340.313,340.778 ccw(c339.745,340.75) 339.745,341.319 ; 340.358,340.607 ccw(c338.602,339.744) 338.602,341.7 ; 340.379,343.572 cw(c338.833,344.541) 338.833,342.716 340.75,342.716 ; 340.441,340.491 ccw(c339.695,339.745) 339.695,340.8 ccw(c339.695,341.855) 340.441,341.109 ccw(c339.695,341.855) 340.75,341.855 ccw(c341.805,341.855) 341.059,341.109 ; 340.531,-126.454 338.88,-126.454 ; 340.75,341.319 339.745,341.319 ; 340.75,342.208 338.602,342.208 ; 340.801,-127.608 cw(c340.34,-127.416) 340.34,-127.915 ; 340.838,-128.204 ccw(c340.34,-128.49) 340.34,-127.915 ; 340.839,-123.603 ccw(c340.349,-123.113) 340.893,-122.685 ; 340.848,-127.915 339.832,-126.899 339.832,-126.645 ; v1@340.902,-88.11 cw(c342.245,-89.454) v1@342.245,-87.554 ; 340.951,-126.645 339.832,-126.645 ; 340.956,-126.118 cw(c339.711,-127.363) 341.4,-127.861 ; 341.416,-122.268 339.705,-123.978 339.578,-123.978 ; v1@341.42,-87.466 ccw(c341.849,-87.036) v1@342.229,-87.51 ; 341.474,-81.442 cw(c344.023,-83.99) 344.023,-80.386 ccw(c344.023,-82.016) 342.871,-80.863 ccw(c341.719,-79.711) 343.348,-79.711 ; v1@341.499,-88.31 cw(c341.879,-88.784) v1@342.309,-88.354 ; v1@341.501,-88.309 cw(c342.31,-89.118) v1@342.31,-87.973 ; v1@341.501,-87.511 cw(c343.492,-89.502) 344.018,-86.736 ; v1@341.507,-88.297 cw(c341.928,-88.408) 341.928,-87.973 ; v1@341.508,-88.291 cw(c343.408,-88.291) v1@342.065,-86.948 ; v1@341.511,-87.536 cw(c342.448,-88.473) 342.448,-87.148 ; v1@341.511,-87.501 ccw(c342.653,-86.36) 342.653,-87.973 ; 341.61,-127.915 340.34,-127.915 ; 341.628,-84.209 342.654,-83.183 ; 341.73,-126.892 cw(c340.906,-127.715) 342.023,-128.044 ; 341.846,-123.107 340.975,-123.978 339.959,-123.978 ; 341.846,-122.858 cw(c341.538,-123.414) 342.174,-123.414 ; 342.118,-83.719 342.118,-81.616 342.654,-81.08 ; 342.174,-127.868 342.174,-127.605 ; v1@342.263,-88.309 cw(c343.072,-89.118) 343.072,-87.973 ; v1@342.263,-87.547 cw(c343.225,-88.509) 343.225,-87.148 cw(c343.225,-85.787) v1@342.263,-86.749 ; v1@342.263,-87.511 ccw(c343.379,-86.396) 343.379,-87.973 ; v1@342.27,-87.528 cw(c343.926,-87.432) 342.753,-86.259 ; v1@342.37,-86.642 cw(c343.77,-88.042) 344.14,-86.097 ; 342.501,-122.858 ccw(c342.81,-123.414) 342.174,-123.414 ; 342.584,-80.332 cw(c344.023,-81.771) 344.023,-79.736 ; 342.603,-87.518 ccw(c342.603,-85.916) 344.001,-86.699 ; 342.631,-87.973 ccw(c342.631,-86.602) 343.998,-86.709 ; 342.924,-127.193 ccw(c342.924,-125.861) 343.866,-126.803 ; 342.946,-127.857 cw(c343.909,-127.386) 343.151,-126.628 ; 342.947,-122.276 ccw(c343.802,-122.602) 343.155,-123.249 ; 342.981,341.109 ccw(c342.235,341.855) 343.29,341.855 ccw(c344.345,341.855) 343.599,341.109 ; 342.981,343.031 cw(c342.235,342.285) 343.29,342.285 cw(c344.345,342.285) 343.599,343.031 ; 342.981,343.649 ccw(c342.235,344.395) 343.29,344.395 ccw(c344.345,344.395) 343.599,343.649 ; 343.103,323.118 cw(c343.103,321.624) 344.16,322.681 ; 343.128,323.796 ccw(c344.241,323.895) 344.241,322.777 ; 343.158,323.121 cw(c343.23,322.254) 343.844,322.869 cw(c344.261,323.286) 343.721,323.523 ; 343.164,323.121 cw(c343.262,322.033) 344.035,322.806 cw(c344.722,323.493) 343.767,323.67 ; 343.216,-87.518 v1(341.494,-87.518) ; 343.29,336.23 343.29,340.8 ; 343.29,337.46 ccw(c344.225,337.46) 343.564,336.799 ; 343.334,-87.973 ccw(c343.334,-86.657) 344.646,-86.76 ; 343.35,-86.658 cw(c341.928,-86.547) 341.928,-87.973 ; 343.353,-86.791 ccw(c342.753,-86.863) 342.753,-86.259 ; 343.405,336.115 343.405,340.685 343.29,340.8 ; 343.405,339.468 ccw(c341.958,339.468) 342.981,340.491 cw(c342.235,339.745) 343.29,339.745 cw(c344.345,339.745) 343.599,340.491 ccw(c344.068,340.022) 343.405,340.022 ; 343.434,-86.381 cw(c341.494,-85.294) v1(341.494,-87.518) ; 343.474,-86.319 cw(c341.864,-85.171) 341.864,-87.148 ; 343.53,-127.571 cw(c344.773,-126.963) 343.794,-125.985 ; 343.546,-87.188 ccw(c342.394,-88.341) 342.394,-86.711 ccw(c342.394,-85.081) 343.546,-86.234 ; 343.555,-122.508 ccw(c344.83,-122.994) 343.865,-123.959 ; 343.571,-86.259 342.753,-86.259 ; 343.58,323.316 cw(c344.732,322.164) 344.732,323.793 cw(c344.732,325.423) 343.58,324.271 ; 343.586,-87.148 341.864,-87.148 ; 343.599,-127.863 cw(c345.481,-127.849) 344.15,-126.518 ; 343.642,-127.026 344.15,-126.518 344.785,-126.518 345.319,-125.985 345.978,-125.985 ; 343.673,-87.288 cw(c343.296,-87.91) 344.023,-87.91 ; 343.683,-123.257 ccw(c342.924,-124.016) 342.924,-122.943 cw(c342.924,-125.243) 344.55,-123.616 ; 343.709,-80.308 cw(c342.548,-82.513) v1@345.039,-82.513 ; 343.749,323.598 cw(c344.698,323.31) 344.698,324.301 ; 343.775,323.854 ccw(c344.952,323.959) 344.952,322.777 ; 343.778,323.793 ccw(c345.543,323.793) 344.295,322.546 ; 343.88,-122.946 cw(c344.558,-122.268) 343.599,-122.268 ccw(c345.784,-122.268) 344.239,-123.813 ; 344.005,-79.729 cw(c343.043,-80.691) 344.404,-80.691 ; 344.011,-79.733 cw(c343.115,-81.436) 345.039,-81.436 ; 344.048,-86.714 cw(c344.799,-86.82) 344.799,-86.061 ; 344.063,322.777 345.46,321.38 345.46,318.205 345.866,317.799 345.866,317.266 ; 344.086,-80.383 cw(c344.196,-81.57) 345.039,-80.727 ; 344.206,-87.402 345.547,-86.061 ; 344.373,-87.288 ccw(c344.75,-87.91) 344.023,-87.91 ; 344.404,-82.26 ccw(c341.474,-82.26) 343.546,-80.188 cw(c342.394,-81.341) 344.023,-81.341 cw(c345.653,-81.341) 344.5,-80.188 ; 344.404,-80.092 344.404,-83.211 344.912,-83.719 347.6,-83.719 348.291,-84.41 348.291,-83.796 347.833,-83.338 345.293,-83.338 345.039,-83.084 v1@345.039,-82.322 ; 344.412,-86.159 ccw(c344.921,-85.436) 345.547,-86.061 ; 344.468,-84.163 348.044,-84.163 ; 344.561,-123.627 ccw(c345.978,-122.211) 345.978,-124.214 ; 344.648,-126.655 cw(c345.978,-127.985) 345.978,-126.104 ; 344.649,329.845 ccw(c342.999,331.496) 345.333,331.496 ; 344.658,-124.334 344.658,-124.232 342.694,-122.268 342.174,-122.268 ; 344.673,-86.061 345.547,-86.061 ; 344.692,-86.805 cw(c345.547,-86.925) 345.547,-86.061 ; 344.695,-79.774 ccw(c345.882,-79.884) 345.039,-80.727 ; 344.989,-126.314 cw(c345.686,-127.012) 345.956,-126.063 ; 345.159,314.984 cw(c343.453,313.277) 345.866,313.277 ; 345.159,315.585 ccw(c343.453,317.292) 345.866,317.292 ; 345.268,-124.334 343.202,-122.268 342.174,-122.268 ; 345.324,328.785 cw(c344.044,327.504) 345.855,327.504 cw(c347.665,327.504) 346.385,328.785 ; 345.324,329.845 ccw(c344.406,330.763) 345.705,330.763 ; 345.333,328.793 345.333,327.73 ; 345.333,330.756 ccw(c346.62,330.756) 345.71,329.845 ; 345.333,334.149 cw(c347.145,334.149) 345.864,335.431 ; 345.333,338.08 ccw(c347.145,338.08) 345.864,336.799 ; 345.333,338.545 cw(c348.084,338.545) 346.139,340.491 ccw(c347.187,339.443) 345.705,339.443 ; 345.333,340.115 cw(c346.515,340.115) 345.679,340.951 ; 345.333,341.085 cw(c348.084,341.085) 346.139,343.031 ccw(c346.885,342.285) 345.83,342.285 ccw(c344.775,342.285) 345.521,343.031 ; 345.333,341.421 ccw(c346.367,341.421) 345.69,340.639 ; 345.333,342.655 cw(c346.515,342.655) 345.679,343.491 ; 345.441,345.365 ccw(c344.691,346.115) 345.747,346.215 ; 345.509,349.462 cw(c344.648,348.601) 345.866,348.601 ; 345.521,340.491 cw(c345.077,340.047) 345.705,340.047 ; 345.521,341.109 ccw(c344.775,341.855) 345.83,341.855 ccw(c346.885,341.855) 346.139,341.109 ; 345.705,329.465 345.705,336.115 345.705,340.675 ; 345.705,331.488 ccw(c348.027,331.488) 346.385,329.845 ; 345.705,331.804 346.476,331.032 346.476,325.317 345.855,324.696 ; 345.83,340.8 345.83,343.34 345.333,342.843 ; 345.847,313.145 cw(c344.941,312.239) 346.222,312.239 ; 345.855,329.315 345.855,324.696 ; 345.857,313.136 cw(c345.342,312.423) 346.222,312.423 ; 345.866,349.656 345.866,347.746 345.866,345.79 345.206,345.129 343.809,345.129 343.29,344.61 343.29,343.34 343.29,340.8 ; 345.973,313.159 ccw(c346.292,312.955) 346.025,312.688 ; v1@345.978,-127.076 345.978,-125.985 ; v1@345.978,-126.727 ccw(c346.735,-126.727) v1@346.2,-127.262 ; 345.978,-124.453 cw(c345.978,-125.479) 346.704,-124.754 ; 345.999,328.785 cw(c344.849,327.634) 346.476,327.634 ; 345.999,329.845 ccw(c344.849,330.996) 346.476,330.996 ; 346.055,-83.338 v1@345.039,-82.322 ; 346.058,306.013 cw(c346.058,304.648) 347.024,305.614 ; 346.116,341.131 cw(c347.597,342.843) 345.333,342.843 ; 346.222,310.966 346.222,311.347 ; 346.465,-105.318 346.465,-101.941 ; 346.476,327.375 cw(c348.47,327.375) 347.06,328.785 ; 346.476,331.032 ccw(c347.963,331.032) 347.01,329.891 ; 346.984,310.611 346.247,311.347 346.222,311.347 ; 347,305.67 ccw(c346.65,305.664) 346.65,306.013 ; 347.119,305.544 346.65,306.013 ; 347.403,-86.386 ccw(c347.403,-85.211) 348.234,-86.042 ; v1(347.452,-128.11) 347.452,-124.74 347.046,-124.334 345.978,-124.334 ; 347.452,-125.502 346.284,-124.334 345.978,-124.334 ; 347.498,317.209 cw(c346.286,315.997) 348,315.997 ; 347.498,347.804 ccw(c346.31,348.992) 347.99,348.992 ; 347.517,345.485 348.37,344.633 348.37,343.34 ; 347.517,347.852 cw(c349.795,347.852) 348.184,349.462 ccw(c348.654,348.993) 347.99,348.993 ; 347.538,317.187 cw(c347.409,316.61) 348,316.61 ; 347.591,-84.163 cw(c347.591,-85.073) 348.234,-84.43 ; 347.637,313.206 cw(c348.88,313.262) 348,314.141 ; 347.637,317.266 cw(c348.721,317.266) 347.954,318.033 ; 347.745,-83.25 cw(c346.622,-84.372) 348.21,-84.372 ; 347.795,349.462 cw(c347.326,348.993) 347.99,348.993 ; 347.833,-86.061 348.291,-86.061 ; 347.845,335.431 cw(c345.94,333.525) 348.635,333.525 ; 347.845,336.799 ccw(c345.94,338.705) 348.635,338.705 ; 347.873,336.625 347.873,341.573 ; 347.873,337.501 ccw(c348.866,337.501) 348.164,336.799 ; 347.873,338.545 cw(c350.624,338.545) 348.679,340.491 ; 347.873,340.115 cw(c349.055,340.115) 348.219,340.951 ; 347.873,341.485 ccw(c349.055,341.485) 348.219,340.649 ; 347.873,341.505 cw(c349.706,341.505) 348.627,342.987 ; 347.873,343.055 ccw(c350.624,343.055) 348.679,341.109 ; 347.873,344.494 ccw(c348.616,344.494) 348.461,343.767 ; 348.005,335.365 cw(c348.005,333.571) 349.273,334.84 ; 348.005,338.863 cw(c350.306,338.863) 348.679,340.491 ; 348.005,340.435 348.005,336.115 348.005,332.933 348.635,332.302 ; 348.05,312.669 ccw(c348.697,313.316) 349.262,312.596 ; 348.061,340.491 cw(c346.675,339.105) 348.635,339.105 ; 348.061,341.109 ccw(c347.315,341.855) 348.37,341.855 ccw(c349.425,341.855) 348.679,341.109 ; 348.061,343.031 cw(c347.315,342.285) 348.37,342.285 cw(c349.425,342.285) 348.679,343.031 cw(c349.425,342.285) 349.425,343.34 cw(c349.425,344.395) 348.679,343.649 ; 348.061,343.649 ccw(c347.315,344.395) 348.37,344.395 ccw(c349.425,344.395) 348.679,343.649 ; 348.089,335.381 cw(c348.369,334.693) 348.894,335.219 ; 348.116,-101.941 v1(348.96,-101.941) ; 348.191,343.225 ccw(c349.59,344.127) 349.59,342.462 ; 348.199,340.927 cw(c349.487,339.967) 349.487,341.573 ; 348.205,322.982 cw(c350.103,321.084) 350.103,323.768 ; 348.212,-86.082 cw(c347.833,-85.998) 347.833,-86.386 345.801,-86.386 ; 348.215,340.654 ccw(c349.029,341.424) 349.029,340.303 ; 348.305,335.89 cw(c347.509,335.094) 348.635,335.094 ; 348.305,336.339 ccw(c347.509,337.136) 348.635,337.136 ; 348.396,322.411 cw(c350.103,320.704) 350.103,323.118 ; 348.458,312.262 347.517,313.202 ; 348.472,323.25 cw(c349.084,322.638) 349.656,323.287 ; 348.508,343.859 350.032,343.859 ; 348.569,312.151 ccw(c349.153,312.735) 349.663,312.085 ; 348.635,332.124 cw(c349.497,332.124) v1@349.153,332.915 ; 348.635,334.224 ccw(c350.43,334.224) v1@349.161,332.955 ; 348.635,335.477 349.143,334.969 349.143,325.571 350.103,324.611 350.103,323.793 ; 348.635,339.668 349.27,340.303 350.54,340.303 ; 348.635,340.535 348.635,332.302 ; 348.687,341.101 ccw(c350.54,342.855) 350.54,340.303 ; 348.72,340.539 cw(c350.783,339) 350.783,341.573 347.873,341.573 ; 348.737,343.577 ccw(c350.783,344.897) 350.783,342.462 348.37,342.462 ; 348.748,343.12 cw(c350.032,342.374) 350.032,343.859 ; 348.77,305.544 348.77,306.513 348,307.283 339.618,307.283 338.856,307.283 338.21,307.93 338.21,340.8 ; 348.962,323.739 cw(c349.543,323.158) 350.086,323.775 ; 349.18,323.196 ccw(c348.583,323.793) 349.428,323.793 ccw(c347.798,323.793) 348.951,324.946 ccw(c350.103,326.098) 350.103,324.468 ; 349.223,311.961 ccw(c348.498,311.236) 348.498,312.262 ccw(c348.498,313.288) 349.223,312.562 ; 349.498,323.494 ccw(c349.016,323.256) 349.016,323.793 ; 349.498,324.093 cw(c349.016,324.331) 349.016,323.793 ; 349.656,325.058 cw(c348.602,324.004) 350.078,323.797 ; 349.661,-84.456 350.144,-83.973 353.981,-83.973 354.387,-84.379 ; 349.719,-84.475 cw(c350.931,-85.687) 350.931,-83.973 ; 349.778,323.793 348,322.015 348,318.078 347.517,317.596 347.517,317.266 348,316.784 348,314.141 347.517,313.659 347.517,313.202 ; 349.824,311.961 cw(c350.55,311.236) 350.55,312.262 cw(c350.55,313.288) 349.824,312.562 ; 349.921,340.303 ccw(c349.921,341.527) 350.786,340.662 ; 349.981,-105.275 349.981,-101.941 ; 350.032,343.467 350.032,343.859 ; 350.173,341.192 cw(c350.173,340.325) 350.786,340.938 ; 350.228,342.97 ccw(c350.228,343.76) 350.786,343.202 ; 350.317,342.97 cw(c350.317,345.287) 348.679,343.649 ; 350.371,341.192 ccw(c350.371,338.798) 348.679,340.491 ; 350.413,343.467 350.413,348.431 ; 350.413,345.224 ccw(c352.532,345.224) 351.034,343.726 ; 350.909,341.192 348.762,341.192 348.37,340.8 ; 350.91,341.954 348.37,341.954 ; 350.91,342.97 348.739,342.97 348.37,343.34 ; 350.91,347.15 356.283,352.523 356.283,353.412 ; 350.91,348.039 350.91,343.34 ; 351.028,349.193 355.865,354.031 ; 351.079,-86.061 346.69,-86.061 ; 351.161,-85.98 348.373,-85.98 348.291,-86.061 ; 351.606,310.491 cw(c351.606,309.159) 352.548,310.101 ; 351.607,312.381 ccw(c351.621,313.188) 352.191,312.617 ; 351.638,310.498 cw(c351.865,309.967) 352.274,310.376 ; 351.663,312.242 cw(c352.569,311.337) 352.569,312.617 ; 351.682,312.27 cw(c352.191,312.071) 352.191,312.617 ; 353.265,309.385 ccw(c354.025,310.146) 354.657,309.274 ; 353.301,-83.973 cw(c353.301,-85.427) 354.33,-84.399 ; 353.45,-105.318 353.45,-101.941 ; 353.773,309.385 ccw(c354.284,309.897) 354.682,309.292 ; 353.803,308.846 ccw(c354.478,309.521) 355.038,308.748 ; 353.886,313.17 cw(c355.053,312.003) 355.053,313.653 ; 353.906,313.19 ccw(c352.768,314.328) 354.378,314.328 ; 354.159,310.141 352.508,310.141 ; 354.43,308.988 cw(c353.969,309.18) 353.969,308.68 ; 354.445,-84.399 cw(c355.094,-85.048) 355.094,-84.13 ; 354.467,308.392 ccw(c353.969,308.106) 353.969,308.68 ; 354.467,312.993 ccw(c353.977,313.482) 354.522,313.911 ; 354.477,308.68 353.461,309.696 353.461,309.95 ; v1@354.53,348.485 cw(c355.874,347.142) v1@355.874,349.041 ; 354.58,309.95 353.461,309.95 ; 354.585,310.478 cw(c353.339,309.232) 355.029,308.735 ; 354.637,-84.13 357.866,-84.13 ; 355.044,314.328 353.334,312.617 353.207,312.617 ; v1@355.048,349.13 ccw(c355.478,349.559) v1@355.858,349.086 ; 355.077,-84.13 cw(c355.077,-85.048) 355.727,-84.399 ; 355.103,355.154 cw(c357.652,352.605) 357.652,356.209 ccw(c357.652,354.58) 356.5,355.732 ccw(c355.347,356.884) 356.977,356.884 ; v1@355.128,348.285 cw(c355.508,347.812) v1@355.937,348.241 ; v1@355.13,348.287 cw(c355.939,347.478) v1@355.939,348.622 ; v1@355.13,349.085 cw(c357.121,347.094) 357.647,349.86 ; v1@355.136,348.298 cw(c355.556,348.187) 355.556,348.622 ; v1@355.137,348.304 cw(c357.037,348.304) v1@355.693,349.648 ; v1@355.14,349.059 cw(c356.077,348.122) 356.077,349.447 ; v1@355.14,349.095 ccw(c356.281,350.236) 356.281,348.622 ; 355.239,308.68 353.969,308.68 ; 355.257,352.386 356.283,353.412 ; 355.359,309.704 cw(c354.535,308.88) 355.652,308.551 ; 355.475,313.489 354.604,312.617 353.588,312.617 ; 355.475,313.738 cw(c355.166,313.181) 355.803,313.181 ; 355.551,-116.162 355.551,-112.743 355.551,-111.219 ; 355.747,352.876 355.747,354.979 356.283,355.515 ; 355.803,308.728 355.803,308.99 ; 355.842,-84.399 cw(c356.491,-85.048) 356.491,-84.13 ; v1@355.892,348.287 cw(c356.701,347.478) 356.701,348.622 ; v1@355.892,349.049 cw(c356.854,348.086) 356.854,349.447 cw(c356.854,350.809) v1@355.892,349.846 ; v1@355.892,349.084 ccw(c357.007,350.2) 357.007,348.622 ; v1@355.899,349.068 cw(c357.555,349.164) 356.382,350.336 ; v1@355.999,349.953 cw(c357.399,348.554) 357.769,350.498 ; 356.13,313.738 ccw(c356.439,313.181) 355.803,313.181 ; 356.213,356.263 cw(c357.652,354.824) 357.652,356.859 ; 356.232,349.077 ccw(c356.232,350.68) 357.63,349.897 ; 356.259,348.622 ccw(c356.259,349.994) 357.627,349.886 ; 356.474,-84.13 cw(c356.474,-85.048) 357.124,-84.399 ; 356.553,309.403 ccw(c356.553,310.735) 357.494,309.793 ; 356.575,308.739 cw(c357.537,309.21) 356.78,309.967 ; 356.576,314.319 ccw(c357.431,313.993) 356.784,313.347 ; 356.844,349.077 v1(355.122,349.077) ; 356.962,348.622 ccw(c356.962,349.939) 358.275,349.836 ; 356.979,349.937 cw(c355.556,350.049) 355.556,348.622 ; 356.982,349.804 ccw(c356.382,349.732) 356.382,350.336 ; 357.063,350.214 cw(c355.123,351.301) v1(355.122,349.077) ; 357.102,350.276 cw(c355.493,351.424) 355.493,349.447 ; 357.154,-114.487 358.893,-114.487 ; 357.159,309.025 cw(c358.401,309.633) 357.423,310.611 ; 357.175,349.407 ccw(c356.022,348.255) 356.022,349.884 ccw(c356.022,351.514) 357.175,350.362 ; 357.183,314.088 ccw(c358.458,313.602) 357.494,312.637 ; 357.2,350.336 356.382,350.336 ; 357.202,-114.439 357.202,-112.743 ; 357.202,-111.219 357.202,-109.765 ; 357.215,349.447 355.493,349.447 ; 357.228,308.733 cw(c359.11,308.747) 357.779,310.077 ; 357.239,-84.399 cw(c357.888,-85.048) 357.888,-84.13 ; 357.271,309.569 357.779,310.077 358.414,310.077 358.947,310.611 359.607,310.611 ; 357.302,349.307 cw(c356.925,348.686) 357.652,348.686 ; 357.312,313.338 ccw(c356.553,312.579) 356.553,313.653 cw(c356.553,311.353) 358.179,312.979 ; 357.337,356.287 cw(c356.177,354.083) v1@358.668,354.083 ; 357.509,313.65 cw(c358.187,314.328) 357.228,314.328 ccw(c359.413,314.328) 357.868,312.783 ; 357.634,356.867 cw(c356.672,355.904) 358.033,355.904 ; 357.64,356.862 cw(c356.744,355.16) 358.668,355.16 ; 357.677,349.881 cw(c358.428,349.775) 358.428,350.534 ; 357.715,356.212 cw(c357.825,355.026) 358.668,355.869 ; 357.835,349.193 359.176,350.534 ; 358.002,349.307 ccw(c358.379,348.686) 357.652,348.686 ; 358.033,354.335 ccw(c355.102,354.335) 357.175,356.407 cw(c356.022,355.255) 357.652,355.255 cw(c359.281,355.255) 358.129,356.407 ; 358.033,356.503 358.033,353.384 358.541,352.876 361.229,352.876 361.92,352.185 361.92,352.799 361.462,353.257 358.922,353.257 358.668,353.511 v1@358.668,354.273 ; 358.041,350.436 ccw(c358.55,351.16) 359.176,350.534 ; 358.096,352.432 361.673,352.432 ; 358.19,312.968 ccw(c359.607,314.385) 359.607,312.381 ; 358.277,309.94 cw(c359.607,308.61) 359.607,310.491 ; 358.287,312.262 358.287,312.363 356.322,314.328 355.803,314.328 ; 358.302,350.534 359.176,350.534 ; 358.303,-114.487 cw(c358.303,-115.222) 358.824,-114.702 ; 358.32,349.791 cw(c359.176,349.67) 359.176,350.534 ; 358.324,356.822 ccw(c359.51,356.711) 358.668,355.869 ; 358.618,310.281 cw(c359.315,309.583) 359.585,310.533 ; 358.744,-104.438 cw(c357.781,-105.401) 359.143,-105.401 cw(c360.505,-105.401) 359.542,-104.438 ; 358.824,-114.354 ccw(c358.082,-113.612) 359.131,-113.612 ; 358.85,-107.907 cw(c358.23,-108.526) 359.107,-108.526 ; 358.896,312.262 356.83,314.328 355.803,314.328 ; 359.107,-119.095 cw(c361.115,-119.095) 360.104,-117.359 ; 359.107,-118.909 359.107,-117.933 359.948,-117.091 ; 359.107,-118.281 cw(c359.987,-118.281) 359.958,-117.401 ; 359.107,-117.964 cw(c360.456,-117.964) 359.777,-116.798 ; 359.107,-117.61 cw(c359.965,-117.61) 359.937,-116.752 ; 359.107,-109.765 359.107,-107.65 ; 359.107,-108.738 cw(c360.282,-108.738) 359.451,-107.907 ; 359.131,-114.459 v1(359.131,-112.04) 359.131,-111.202 ; v1(359.143,-105.556) 359.143,-103.658 ; v1@359.607,309.519 359.607,310.611 ; v1@359.607,309.868 ccw(c360.364,309.868) v1@359.829,309.333 ; 359.607,312.142 cw(c359.607,311.116) 360.333,311.842 ; 359.638,-117.091 cw(c358.89,-117.091) 359.419,-117.621 cw(c359.948,-118.15) 359.948,-117.401 ; 359.684,353.257 v1@358.668,354.273 ; 360.094,331.277 360.094,334.654 ; 360.758,-118.909 362.917,-118.909 362.917,-119.63 363.327,-120.041 v1(363.581,-120.041) ; 360.758,-109.765 360.758,-112.781 360.948,-112.972 360.948,-114.591 ; 360.76,-112.861 cw(c360.307,-113.315) 360.948,-113.315 ; 360.774,-114.354 ccw(c360.353,-113.933) 360.948,-113.933 ccw(c361.543,-113.933) 361.122,-114.354 ; 361.031,350.209 ccw(c361.031,351.385) 361.862,350.554 ; v1(361.081,308.486) 361.081,311.855 360.674,312.262 359.607,312.262 ; 361.081,311.093 359.912,312.262 359.607,312.262 ; 361.22,352.432 cw(c361.22,351.523) 361.862,352.166 ; 361.373,353.346 cw(c360.251,352.223) 361.838,352.223 ; 361.462,350.534 361.92,350.534 ; 361.745,334.654 v1(362.589,334.654) ; 361.84,350.514 cw(c361.462,350.597) 361.462,350.209 359.43,350.209 ; 362.279,-107.306 ccw(c361.553,-106.58) 362.579,-106.58 ccw(c363.605,-106.58) 362.88,-107.306 ccw(c363.605,-106.58) 363.605,-107.606 ccw(c363.605,-108.632) 362.88,-107.907 ; 362.679,-112.797 cw(c362.258,-113.218) 362.853,-113.218 cw(c363.448,-113.218) 363.027,-112.797 ; 362.73,-105.271 cw(c364.343,-106.884) 364.343,-104.603 ; 362.853,-114.528 362.853,-112.559 ; 363.105,-119.819 ccw(c363.581,-119.342) v1@363.581,-120.016 ; 363.29,352.14 363.772,352.622 367.609,352.622 368.016,352.216 ; 363.347,352.12 cw(c364.56,350.908) 364.56,352.622 ; 363.581,-128.806 v1(363.581,-127.28) ; 363.61,331.32 363.61,334.654 ; 363.634,-109.84 ccw(c363.105,-109.311) 363.853,-109.311 ccw(c364.601,-109.311) 364.072,-109.84 ; 363.853,-110.059 363.853,-107.749 ; 364.343,-103.658 362.579,-105.422 362.579,-107.606 365.246,-107.606 ; 364.568,-116.75 364.568,-118.909 366.854,-118.909 ; 364.708,350.534 360.319,350.534 ; 364.789,350.616 362.002,350.616 361.92,350.534 ; 364.946,-107.907 ccw(c364.22,-108.632) 364.22,-107.606 ccw(c364.22,-106.58) 364.946,-107.306 ; v1(365.291,-128.11) 366.107,-127.294 v1(366.107,-126.264) ; v1(366.121,-101.118) 367.201,-101.118 ; 366.87,-112.797 cw(c366.449,-113.218) 367.044,-113.218 cw(c367.639,-113.218) 367.218,-112.797 ; 366.93,352.622 cw(c366.93,351.169) 367.958,352.197 ; 367.044,-112.559 367.044,-113.631 368.044,-114.631 370.623,-114.631 370.727,-114.528 ; 367.079,331.277 367.079,334.654 ; 367.137,-102.039 ccw(c368.012,-102.039) 367.393,-102.658 ; 367.137,-101.118 367.137,-102.814 367.219,-102.896 ; 367.734,-114.631 ccw(c366.986,-114.631) 367.515,-114.102 ccw(c368.044,-113.573) 368.044,-114.321 ; 367.95,-105.615 cw(c366.198,-107.367) 368.675,-107.367 ; 368.073,352.197 cw(c368.723,351.548) 368.723,352.465 ; 368.169,-105.396 368.675,-105.902 368.675,-107.606 ; 368.263,-114.851 cw(c368.792,-115.38) 368.792,-114.631 cw(c368.792,-113.883) 368.263,-114.412 ; 368.265,352.465 371.495,352.465 ; 368.375,-107.306 ccw(c367.649,-106.58) 368.675,-106.58 ccw(c369.701,-106.58) 368.976,-107.306 ; 368.41,-105.156 cw(c367.768,-105.797) 368.675,-105.797 ; 368.706,352.465 cw(c368.706,351.548) 369.355,352.197 ; 368.832,-101.176 cw(c368.019,-101.989) 369.169,-101.989 ; 368.852,-101.118 369.169,-101.435 369.169,-102.896 ; 368.994,-117.131 368.994,-117.453 v1(369.804,-118.263) ; 368.995,-102.658 ccw(c368.574,-102.237) 369.169,-102.237 ccw(c369.764,-102.237) 369.343,-102.658 ; 369.179,320.434 369.179,323.852 369.179,325.376 ; 369.241,-117.195 ccw(c370.458,-117.195) v1@369.597,-118.056 ; v1@369.28,-127.28 v1(369.28,-127.153) 369.28,-126.179 369.779,-125.68 ; v1@369.28,-127.199 cw(c371.004,-127.199) 369.858,-125.911 ; 369.47,352.197 cw(c370.12,351.548) 370.12,352.465 ; 370.103,352.465 cw(c370.103,351.548) 370.752,352.197 ; 370.783,322.109 372.522,322.109 ; 370.83,322.156 370.83,323.852 ; 370.83,325.376 370.83,326.83 ; 370.867,352.197 cw(c371.517,351.548) 371.517,352.465 ; 371.932,322.109 cw(c371.932,321.373) 372.452,321.893 ; 372.373,332.158 cw(c371.41,331.195) 372.772,331.195 cw(c374.134,331.195) 373.171,332.158 ; 372.452,322.242 ccw(c371.711,322.984) 372.76,322.984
